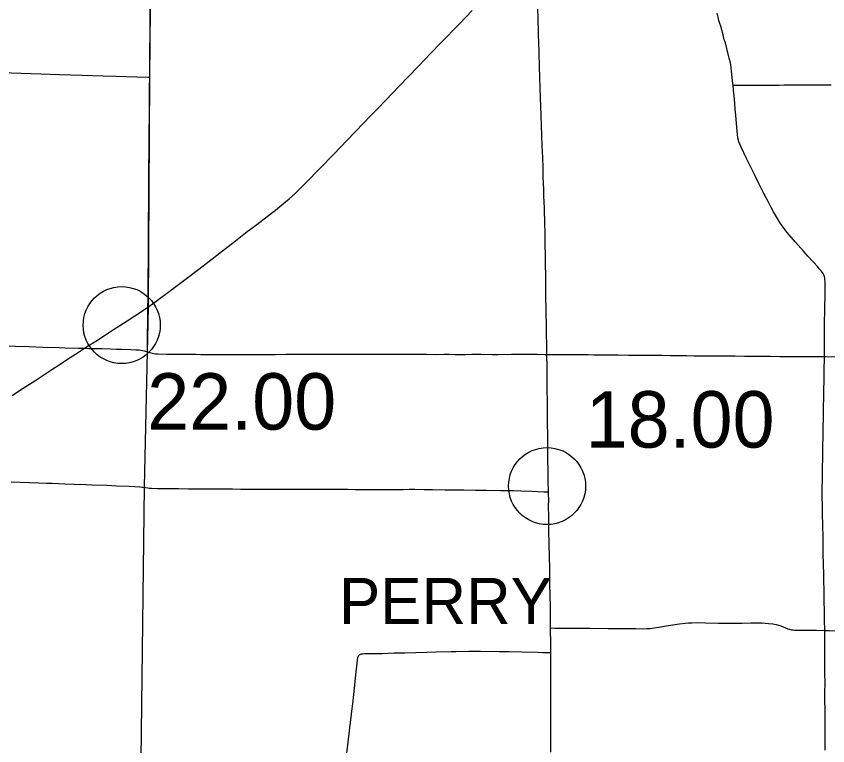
# Model space of a CAD drawing. Extents: x 1813937 to 1948437, y 826606 to 1022856.
# Drawn here: x 1913070 to 1928879, y 939932 to 954153 of the extents above; entities that cross this region are included whole.
import ezdxf

# ---------------------------------------------------------------- set-up
doc = ezdxf.new("R2010")
doc.units = 0
for name, color, linetype in [('Default', 7, 'Continuous'), ('GM_X_County_Road', 7, 'Continuous'), ('GM_X_State_Route', 7, 'Continuous'), ('GM_X_Township', 7, 'Continuous'), ('GM_X_Township_Road', 7, 'Continuous'), ('GM_X_Township_Text', 7, 'Continuous'), ('GM_X_US_Route', 7, 'Continuous')]:
    doc.layers.add(name, color=color, linetype=linetype)

msp = doc.modelspace()

# ---------------------------------------------------------------- linework, layer by layer
at = {"layer": 'Default'}
for centre in [(1915125, 948132), (1923411, 944994)]:
    msp.add_circle(centre, 750, dxfattribs=at)
at = {"layer": 'GM_X_County_Road'}
for points in [[(1915670, 952967), (1915670, 952983), (1915670, 953098), (1915673, 953312), (1915675, 953525), (1915676, 953755), (1915681, 954215), (1915682, 954412), (1915683, 954576), (1915683, 954707), (1915686, 955036), (1915690, 955266), (1915691, 955430), (1915693, 955551), (1915693, 955599)], [(1915635, 948484), (1915639, 948648), (1915640, 948829), (1915642, 949108), (1915644, 949371), (1915645, 949568), (1915644, 949699), (1915644, 949830), (1915646, 950011), (1915648, 950159), (1915649, 950274), (1915653, 950405), (1915655, 950783), (1915656, 951013), (1915656, 951259), (1915658, 951456), (1915659, 951670), (1915660, 951883), (1915663, 952212), (1915665, 952474), (1915667, 952753), (1915670, 952967)], [(1915625, 947609), (1915626, 947637), (1915627, 947775), (1915630, 947972), (1915635, 948153), (1915637, 948269), (1915636, 948351), (1915636, 948466), (1915635, 948484)], [(1910365, 947816), (1910498, 947813), (1910842, 947800), (1911137, 947790), (1911350, 947783), (1911580, 947775), (1911744, 947768), (1911941, 947760), (1912104, 947754), (1912301, 947748), (1912662, 947734), (1913055, 947722), (1913318, 947713), (1913597, 947703), (1913908, 947695), (1914023, 947692), (1914285, 947685), (1914367, 947681), (1914402, 947680)], [(1914402, 947680), (1914482, 947679), (1914744, 947673), (1914908, 947667), (1915023, 947663), (1915121, 947662), (1915302, 947656), (1915400, 947652), (1915466, 947647), (1915498, 947643), (1915531, 947637), (1915563, 947629), (1915625, 947609)], [(1915625, 947609), (1915673, 947595), (1915720, 947583), (1915752, 947577), (1915784, 947572), (1915833, 947569), (1915997, 947567), (1916177, 947565), (1916292, 947565), (1916390, 947564), (1916571, 947563), (1916669, 947562), (1916932, 947560), (1917112, 947560), (1917292, 947559), (1917423, 947559), (1917505, 947560), (1917604, 947562), (1917702, 947562), (1917800, 947561), (1917866, 947560), (1917931, 947560), (1918062, 947561), (1918111, 947561), (1918325, 947563), (1918407, 947563), (1918571, 947564), (1918685, 947563), (1918800, 947564), (1918882, 947564), (1919259, 947564), (1919358, 947564), (1919473, 947565), (1919554, 947565), (1919636, 947566), (1919850, 947567), (1919981, 947567), (1920161, 947566), (1920489, 947563), (1920637, 947565), (1920735, 947566), (1921063, 947564), (1921260, 947562), (1921408, 947564), (1921506, 947564), (1921621, 947562), (1921702, 947562), (1921816, 947562), (1921948, 947563), (1922128, 947563), (1922341, 947561), (1922456, 947562), (1922718, 947563), (1923047, 947563), (1923226, 947563), (1923372, 947561), (1923409, 947561)], [(1923409, 947561), (1923536, 947562), (1923684, 947562), (1923946, 947559), (1924077, 947557), (1924209, 947556), (1924323, 947554), (1924438, 947552), (1924569, 947552), (1924733, 947550), (1924799, 947550), (1924995, 947547), (1925094, 947546), (1925258, 947545), (1925405, 947544), (1925651, 947543), (1925815, 947540), (1925979, 947539), (1926127, 947537), (1926274, 947536), (1926389, 947536), (1926504, 947536), (1926652, 947533), (1926848, 947533), (1927078, 947531), (1927258, 947529), (1927390, 947527), (1927537, 947527), (1927767, 947524), (1927947, 947523), (1928029, 947523), (1928226, 947522), (1928603, 947519), (1928814, 947518)], [(1928814, 947518), (1928833, 947518), (1929178, 947515), (1929325, 947513), (1929424, 947512), (1929555, 947510), (1929653, 947510), (1929801, 947509), (1930080, 947506), (1930309, 947506), (1930555, 947507), (1930654, 947508), (1930851, 947509), (1931047, 947507), (1931244, 947506), (1931286, 947506)]]:
    msp.add_lwpolyline(points, dxfattribs=at)
at = {"layer": 'GM_X_State_Route'}
for points in [[(1923255, 953496), (1923252, 953597), (1923246, 953843), (1923239, 954106), (1923232, 954302), (1923228, 954433), (1923226, 954515), (1923222, 954679), (1923219, 954744), (1923217, 954757), (1923217, 954825), (1923212, 954972), (1923208, 955102), (1923207, 955195), (1923207, 955247), (1923206, 955282), (1923204, 955361), (1923201, 955436), (1923201, 955460), (1923199, 955525), (1923199, 955548)], [(1923416, 946828), (1923415, 946875), (1923414, 947039), (1923414, 947203), (1923412, 947367), (1923409, 947515), (1923409, 947561), (1923408, 947646), (1923406, 947777), (1923403, 947925), (1923399, 948171), (1923395, 948319), (1923393, 948466), (1923390, 948646), (1923386, 948974), (1923384, 949122), (1923382, 949286), (1923381, 949450), (1923375, 949745), (1923372, 949958), (1923368, 950089), (1923358, 950417), (1923350, 950647), (1923345, 950778), (1923338, 951024), (1923333, 951188), (1923326, 951401), (1923318, 951630), (1923295, 952220), (1923290, 952401), (1923282, 952565), (1923276, 952761), (1923269, 952958), (1923263, 953171), (1923256, 953433), (1923255, 953496)], [(1923442, 944632), (1923443, 944695), (1923440, 944875), (1923440, 944880), (1923434, 945105), (1923431, 945318), (1923429, 945481), (1923427, 945662), (1923425, 945809), (1923425, 945941), (1923423, 946039), (1923422, 946170), (1923420, 946416), (1923417, 946695), (1923416, 946828)], [(1923486, 939807), (1923485, 940021), (1923485, 940168), (1923485, 940513), (1923485, 940660), (1923485, 940906), (1923484, 941152), (1923483, 941431), (1923483, 941611), (1923483, 941752), (1923482, 941923), (1923479, 942202), (1923478, 942230), (1923475, 942579), (1923468, 942924), (1923467, 943022), (1923466, 943186), (1923462, 943383), (1923457, 943629), (1923453, 943858), (1923448, 944137), (1923443, 944400), (1923442, 944596), (1923442, 944632)]]:
    msp.add_lwpolyline(points, dxfattribs=at)
at = {"layer": 'GM_X_Township'}
msp.add_lwpolyline([(1889423, 961536), (1894728, 961453), (1894730, 961440), (1894815, 961451), (1899962, 961375), (1907847, 961159), (1910485, 961083), (1915744, 960965), (1915744, 960672), (1915689, 955598), (1915669, 952972), (1915640, 948490), (1915630, 947868), (1915624, 947610), (1915561, 944982), (1915495, 939674)], dxfattribs=at)
at = {"layer": 'GM_X_Township_Road'}
for points in [[(1927033, 952806), (1927029, 952841), (1927018, 952955), (1927005, 953084), (1926998, 953149), (1926988, 953212), (1926982, 953243), (1926959, 953338), (1926939, 953416), (1926931, 953447), (1926928, 953462), (1926912, 953525), (1926884, 953634), (1926875, 953665), (1926864, 953695), (1926849, 953758), (1926840, 953789), (1926828, 953836), (1926821, 953868), (1926812, 953899), (1926806, 953914), (1926793, 953961), (1926788, 953976), (1926782, 953991), (1926759, 954070), (1926743, 954134), (1926727, 954214)], [(1910427, 953140), (1910699, 953130), (1910977, 953122), (1911371, 953109), (1911699, 953099), (1911977, 953091), (1912600, 953066), (1912715, 953060), (1912977, 953051), (1913551, 953030), (1913911, 953017), (1914354, 953002), (1914764, 952989), (1915010, 952982), (1915420, 952971), (1915633, 952967), (1915670, 952967)], [(1927033, 952806), (1927089, 952808), (1927137, 952807), (1927388, 952808), (1927536, 952810), (1927651, 952810), (1927782, 952811), (1927929, 952811), (1928027, 952813), (1928142, 952813), (1928273, 952815), (1928584, 952818), (1928699, 952817), (1928945, 952814)], [(1928814, 947518), (1928814, 947608), (1928815, 947741), (1928815, 947883), (1928818, 948145), (1928821, 948458), (1928826, 948737), (1928828, 948868), (1928827, 948982), (1928824, 949021), (1928822, 949050), (1928815, 949079), (1928809, 949095), (1928800, 949112), (1928787, 949138), (1928767, 949164), (1928748, 949188), (1928732, 949207), (1928712, 949229), (1928676, 949272), (1928606, 949350), (1928582, 949377), (1928493, 949477), (1928407, 949575), (1928252, 949750), (1928126, 949891), (1928063, 949972), (1928029, 950015), (1927993, 950064), (1927947, 950132), (1927899, 950210), (1927824, 950339), (1927768, 950440), (1927723, 950527), (1927631, 950700), (1927534, 950890), (1927452, 951069), (1927402, 951172), (1927351, 951275), (1927299, 951377), (1927192, 951598), (1927165, 951658), (1927147, 951705), (1927138, 951737), (1927129, 951785), (1927120, 951850), (1927108, 951981), (1927085, 952226), (1927076, 952339), (1927066, 952453), (1927059, 952534), (1927041, 952713), (1927033, 952806)], [(1928819, 942182), (1928819, 942189), (1928817, 942376), (1928813, 942573), (1928809, 942737), (1928808, 942786), (1928806, 942884), (1928806, 942966), (1928803, 943147), (1928800, 943245), (1928794, 943507), (1928792, 943638), (1928789, 943786), (1928788, 943851), (1928788, 943950), (1928787, 944015), (1928783, 944212), (1928782, 944310), (1928778, 944375), (1928774, 944556), (1928773, 944851), (1928773, 944982), (1928775, 945098), (1928778, 945293), (1928784, 945605), (1928786, 945752), (1928788, 945982), (1928789, 946146), (1928794, 946310), (1928795, 946441), (1928798, 946556), (1928800, 946703), (1928803, 946850), (1928807, 947063), (1928812, 947260), (1928814, 947489), (1928814, 947518)], [(1912974, 945078), (1913149, 945072), (1913510, 945059), (1913658, 945054), (1913773, 945051), (1914019, 945039), (1914200, 945032), (1914429, 945023), (1914544, 945019), (1914840, 945010), (1915021, 945002), (1915267, 944993), (1915382, 944987), (1915480, 944979), (1915529, 944973), (1915538, 944971)], [(1915538, 944971), (1915632, 944959)], [(1915632, 944959), (1915659, 944955), (1915708, 944951), (1915823, 944947), (1915970, 944946), (1916085, 944946), (1916232, 944946), (1916429, 944943), (1916659, 944942), (1916855, 944942), (1917085, 944941), (1917281, 944938), (1917445, 944937), (1917740, 944937), (1917937, 944935), (1918117, 944933), (1918281, 944932), (1918527, 944933), (1918675, 944933), (1918822, 944933), (1918937, 944934), (1919084, 944934), (1919183, 944932), (1919281, 944932), (1919412, 944931), (1919527, 944931), (1919674, 944929), (1919805, 944929), (1920018, 944929), (1920199, 944930), (1920362, 944930), (1920608, 944930), (1920723, 944931), (1920838, 944931), (1921018, 944927), (1921182, 944928), (1921428, 944924), (1921788, 944922), (1922018, 944917), (1922231, 944915), (1922510, 944910), (1922755, 944906), (1922903, 944903), (1923116, 944893), (1923345, 944883), (1923411, 944881), (1923440, 944880)], [(1923478, 942230), (1923563, 942227), (1923662, 942226), (1923810, 942227), (1923990, 942226), (1924122, 942224), (1924253, 942222), (1924598, 942221), (1924828, 942218), (1924992, 942216), (1925140, 942215), (1925288, 942213), (1925354, 942215), (1925420, 942221), (1925501, 942232), (1925777, 942275), (1925988, 942307), (1926102, 942323), (1926167, 942329), (1926233, 942331), (1926348, 942332), (1926495, 942329), (1926742, 942324), (1926873, 942323), (1927103, 942323), (1927202, 942324), (1927382, 942326), (1927497, 942328), (1927596, 942328), (1927661, 942325), (1927726, 942318), (1927807, 942306), (1927871, 942293), (1927919, 942282), (1927966, 942268), (1928012, 942251), (1928103, 942213), (1928135, 942203), (1928167, 942195), (1928199, 942189), (1928232, 942186), (1928265, 942184), (1928430, 942185), (1928659, 942183), (1928819, 942182)], [(1928829, 939845), (1928829, 939960), (1928829, 940139), (1928829, 940238), (1928827, 940434), (1928826, 940533), (1928826, 940647), (1928825, 940811), (1928825, 940941), (1928826, 941187), (1928825, 941318), (1928825, 941432), (1928823, 941530), (1928822, 941629), (1928821, 941741), (1928820, 941888), (1928820, 942068), (1928819, 942182)], [(1928819, 942182), (1928912, 942180), (1929124, 942173), (1929239, 942169), (1929402, 942164), (1929550, 942160), (1929648, 942158), (1929746, 942158), (1929893, 942160), (1930187, 942166), (1930378, 942171), (1930492, 942171), (1930594, 942168), (1930694, 942167), (1930776, 942163), (1930842, 942162), (1930940, 942164), (1930989, 942164), (1931070, 942164), (1931267, 942162), (1931414, 942160), (1931528, 942157), (1931752, 942154)], [(1919769, 941713), (1919779, 941718), (1919793, 941722), (1919808, 941725), (1919824, 941726), (1919857, 941728), (1920201, 941734), (1920430, 941742), (1920643, 941747), (1920856, 941752), (1921069, 941760), (1921249, 941766), (1921544, 941771), (1921642, 941772), (1921888, 941775), (1922117, 941775), (1922478, 941772), (1922674, 941767), (1922920, 941764), (1923232, 941757), (1923330, 941753), (1923412, 941751), (1923483, 941752)], [(1919490, 939617), (1919501, 939677), (1919506, 939711), (1919519, 939840), (1919535, 940003), (1919553, 940166), (1919567, 940280), (1919581, 940394), (1919594, 940492), (1919607, 940606), (1919626, 940753), (1919646, 940932), (1919666, 941112), (1919682, 941259), (1919720, 941602), (1919727, 941650), (1919731, 941665), (1919737, 941680), (1919746, 941692), (1919760, 941706), (1919769, 941713)]]:
    msp.add_lwpolyline(points, dxfattribs=at)
at = {"layer": 'GM_X_US_Route'}
for points in [[(1921433, 953726), (1921463, 953758), (1921577, 953876), (1921692, 953993), (1921829, 954134), (1921955, 954263)], [(1912994, 946763), (1913136, 946855), (1913453, 947060), (1913782, 947277), (1913906, 947357), (1914071, 947465), (1914222, 947563), (1914402, 947680), (1914470, 947725), (1914621, 947822), (1914787, 947929), (1914965, 948046), (1915090, 948124), (1915229, 948213), (1915530, 948411), (1915635, 948484), (1915652, 948495), (1915825, 948620), (1916048, 948787), (1916364, 949023), (1916624, 949223), (1917027, 949534), (1917339, 949774), (1917572, 949955), (1917729, 950074), (1917898, 950204), (1918043, 950312), (1918121, 950372), (1918247, 950477), (1918385, 950594), (1918495, 950692), (1918602, 950794), (1918708, 950898), (1918993, 951193), (1919254, 951465), (1919517, 951737), (1919835, 952068), (1919984, 952221), (1920120, 952363), (1920269, 952515), (1920528, 952789), (1920701, 952965), (1920905, 953178), (1921156, 953438), (1921338, 953628), (1921433, 953726)]]:
    msp.add_lwpolyline(points, dxfattribs=at)

# ---------------------------------------------------------------- texts
at = {"layer": 'Default'}
for s, p in [('22.00', (1915622, 946094)), ('18.00', (1924161, 945744))]:
    msp.add_text(s, height=1100, dxfattribs=at).set_placement(p)
at = {"layer": 'GM_X_Township_Text'}
msp.add_text('PERRY', height=900, rotation=0, dxfattribs=at).set_placement((1919359, 942304))

doc.saveas('drawing.dxf')
